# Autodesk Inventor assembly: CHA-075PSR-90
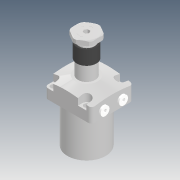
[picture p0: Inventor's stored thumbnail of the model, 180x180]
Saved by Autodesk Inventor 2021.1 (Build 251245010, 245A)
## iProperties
Created: 2018-11
Part Number: CHA-075PSR-90
Description: STEP AP214
Document SubType Name: Assembly
Designer: user
Title: CHA-075PSR-90.STEP
Revision Number: ÈÎºÎ
Sending System: SolidWorks 2016
Preprocessor: SwSTEP 2.0
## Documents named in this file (7)
- D:\Vault_2016\Projekty\Clamptek\Hydraulic\CHA-P\Inventor\CHA-075PSR-90\CHA-075PSR-90.iam
- D:\Vault_2016\Projekty\Clamptek\Hydraulic\CHA-P\Inventor\CHA-075PSR-90\CHA-075P(BT).ipt
- D:\Vault_2016\Projekty\Clamptek\Hydraulic\CHA-P\Inventor\CHA-075PSR-90\¶ÂÍ·G4-1.ipt
- D:\Vault_2016\Projekty\Clamptek\Hydraulic\CHA-P\Inventor\CHA-075PSR-90\CHA-075P(XIAO).ipt
- D:\Vault_2016\Projekty\Clamptek\Hydraulic\CHA-P\Inventor\CHA-075PSR-90\CHA-075PS(LM).ipt
- D:\Vault_2016\Projekty\Clamptek\Hydraulic\CHA-P\Inventor\CHA-075PSR-90\CHA-075P(ZH).ipt
- D:\Vault_2016\Projekty\Clamptek\Hydraulic\CHA-P\Inventor\CHA-075PSR-90\CHA-075PS(HSG).ipt
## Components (7 placed, 7 different names)
1. CHA-075P(BT)_1
2. ¶ÂÍ·G4-1_2
3. ¶ÂÍ·G4-1_3
4. CHA-075P(XIAO)_4
5. CHA-075PS(LM)_5
6. CHA-075P(ZH)_6
7. CHA-075PS(HSG)_7
